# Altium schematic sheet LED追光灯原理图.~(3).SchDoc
size A3
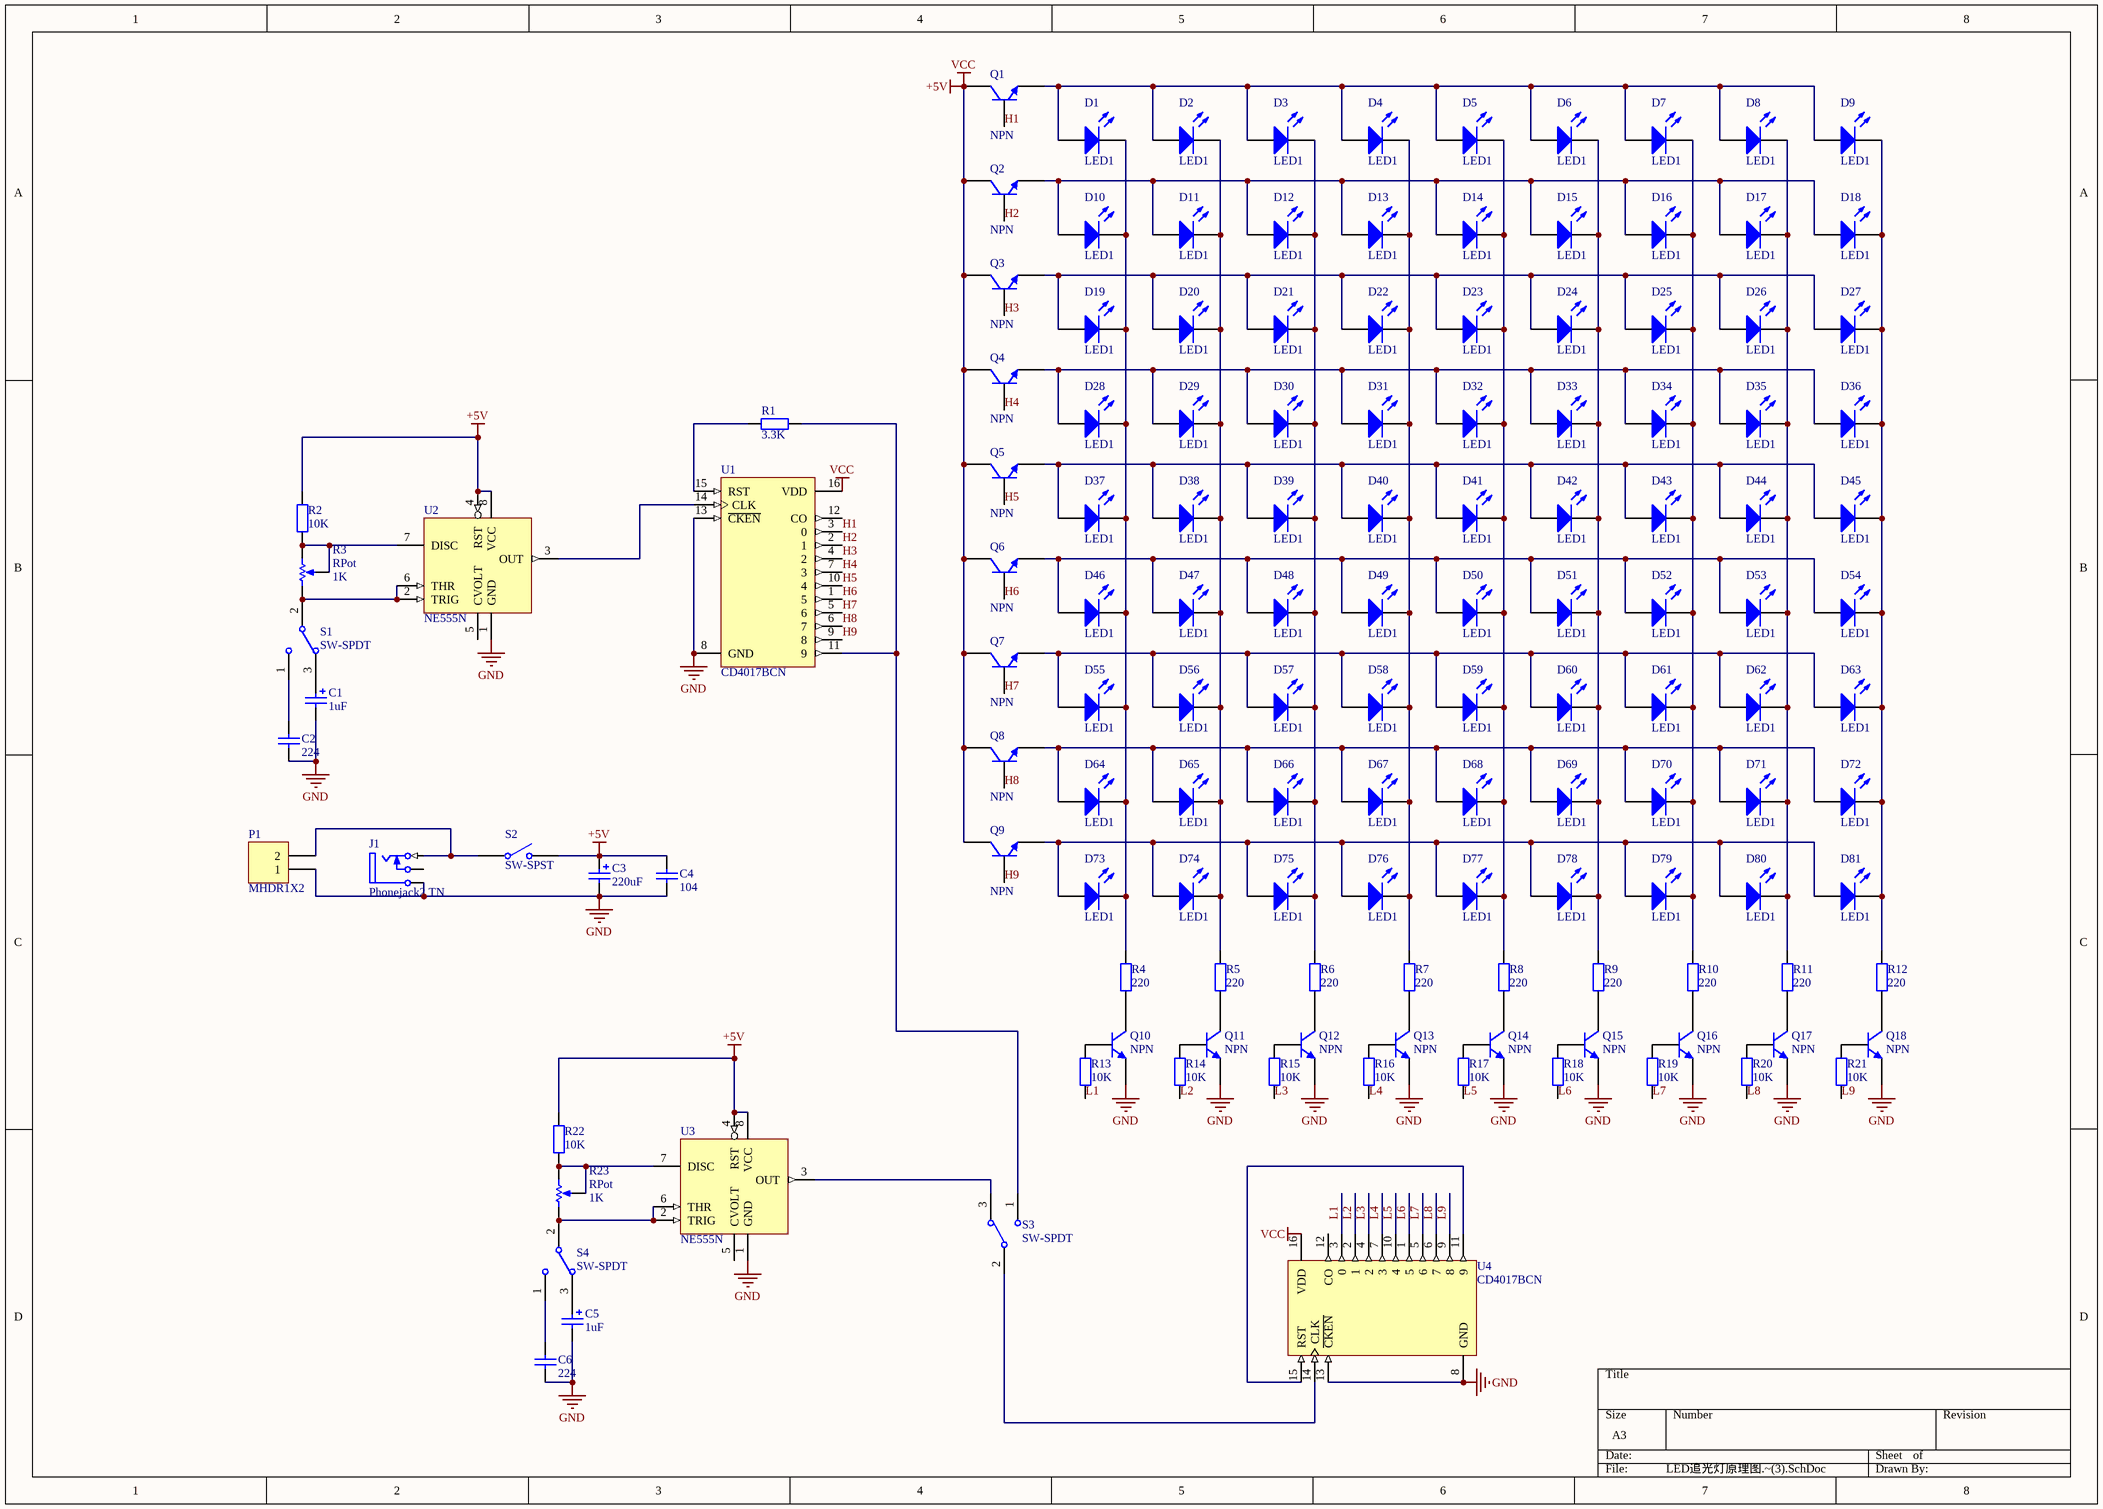
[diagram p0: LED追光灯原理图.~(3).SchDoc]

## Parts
C1  value 1uF  [POLAR0.8]  (hidden comment: Cap Pol2)
C2  value 224  [RAD-0.3]  (hidden comment: Cap)
C3  value 220uF  [POLAR0.8]  (hidden comment: Cap Pol2)
C4  value 104  [RAD-0.3]  (hidden comment: Cap)
C5  value 1uF  [POLAR0.8]  (hidden comment: Cap Pol2)
C6  value 224  [RAD-0.3]  (hidden comment: Cap)
D1  LED1  [LED-1]
D2  LED1  [LED-1]
D3  LED1  [LED-1]
D4  LED1  [LED-1]
D5  LED1  [LED-1]
D6  LED1  [LED-1]
D7  LED1  [LED-1]
D8  LED1  [LED-1]
D9  LED1  [LED-1]
D10  LED1  [LED-1]
D11  LED1  [LED-1]
D12  LED1  [LED-1]
D13  LED1  [LED-1]
D14  LED1  [LED-1]
D15  LED1  [LED-1]
D16  LED1  [LED-1]
D17  LED1  [LED-1]
D18  LED1  [LED-1]
D19  LED1  [LED-1]
D20  LED1  [LED-1]
D21  LED1  [LED-1]
D22  LED1  [LED-1]
D23  LED1  [LED-1]
D24  LED1  [LED-1]
D25  LED1  [LED-1]
D26  LED1  [LED-1]
D27  LED1  [LED-1]
D28  LED1  [LED-1]
D29  LED1  [LED-1]
D30  LED1  [LED-1]
D31  LED1  [LED-1]
D32  LED1  [LED-1]
D33  LED1  [LED-1]
D34  LED1  [LED-1]
D35  LED1  [LED-1]
D36  LED1  [LED-1]
D37  LED1  [LED-1]
D38  LED1  [LED-1]
D39  LED1  [LED-1]
D40  LED1  [LED-1]
D41  LED1  [LED-1]
D42  LED1  [LED-1]
D43  LED1  [LED-1]
D44  LED1  [LED-1]
D45  LED1  [LED-1]
D46  LED1  [LED-1]
D47  LED1  [LED-1]
D48  LED1  [LED-1]
D49  LED1  [LED-1]
D50  LED1  [LED-1]
D51  LED1  [LED-1]
D52  LED1  [LED-1]
D53  LED1  [LED-1]
D54  LED1  [LED-1]
D55  LED1  [LED-1]
D56  LED1  [LED-1]
D57  LED1  [LED-1]
D58  LED1  [LED-1]
D59  LED1  [LED-1]
D60  LED1  [LED-1]
D61  LED1  [LED-1]
D62  LED1  [LED-1]
D63  LED1  [LED-1]
D64  LED1  [LED-1]
D65  LED1  [LED-1]
D66  LED1  [LED-1]
D67  LED1  [LED-1]
D68  LED1  [LED-1]
D69  LED1  [LED-1]
D70  LED1  [LED-1]
D71  LED1  [LED-1]
D72  LED1  [LED-1]
D73  LED1  [LED-1]
D74  LED1  [LED-1]
D75  LED1  [LED-1]
D76  LED1  [LED-1]
D77  LED1  [LED-1]
D78  LED1  [LED-1]
D79  LED1  [LED-1]
D80  LED1  [LED-1]
D81  LED1  [LED-1]
J1  Phonejack2 TN  [JACK/6-V3A]
P1  MHDR1X2  [MHDR1X2]
Q1  NPN  [TO-226-AA]
Q2  NPN  [TO-226-AA]
Q3  NPN  [TO-226-AA]
Q4  NPN  [TO-226-AA]
Q5  NPN  [TO-226-AA]
Q6  NPN  [TO-226-AA]
Q7  NPN  [TO-226-AA]
Q8  NPN  [TO-226-AA]
Q9  NPN  [TO-226-AA]
Q10  NPN  [TO-226-AA]
Q11  NPN  [TO-226-AA]
Q12  NPN  [TO-226-AA]
Q13  NPN  [TO-226-AA]
Q14  NPN  [TO-226-AA]
Q15  NPN  [TO-226-AA]
Q16  NPN  [TO-226-AA]
Q17  NPN  [TO-226-AA]
Q18  NPN  [TO-226-AA]
R1  value 3.3K  [AXIAL-0.4]  (hidden comment: Res2)
R2  value 10K  [AXIAL-0.4]  (hidden comment: Res2)
R3  RPot  value 1K  [VR5]
R4  value 220  [AXIAL-0.4]  (hidden comment: Res2)
R5  value 220  [AXIAL-0.4]  (hidden comment: Res2)
R6  value 220  [AXIAL-0.4]  (hidden comment: Res2)
R7  value 220  [AXIAL-0.4]  (hidden comment: Res2)
R8  value 220  [AXIAL-0.4]  (hidden comment: Res2)
R9  value 220  [AXIAL-0.4]  (hidden comment: Res2)
R10  value 220  [AXIAL-0.4]  (hidden comment: Res2)
R11  value 220  [AXIAL-0.4]  (hidden comment: Res2)
R12  value 220  [AXIAL-0.4]  (hidden comment: Res2)
R13  value 10K  [AXIAL-0.4]  (hidden comment: Res2)
R14  value 10K  [AXIAL-0.4]  (hidden comment: Res2)
R15  value 10K  [AXIAL-0.4]  (hidden comment: Res2)
R16  value 10K  [AXIAL-0.4]  (hidden comment: Res2)
R17  value 10K  [AXIAL-0.4]  (hidden comment: Res2)
R18  value 10K  [AXIAL-0.4]  (hidden comment: Res2)
R19  value 10K  [AXIAL-0.4]  (hidden comment: Res2)
R20  value 10K  [AXIAL-0.4]  (hidden comment: Res2)
R21  value 10K  [AXIAL-0.4]  (hidden comment: Res2)
R22  value 10K  [AXIAL-0.4]  (hidden comment: Res2)
R23  RPot  value 1K  [VR5]
S1  SW-SPDT  [TL36WW15050]
S2  SW-SPST  [SPST-2]
S3  SW-SPDT  [TL36WW15050]
S4  SW-SPDT  [TL36WW15050]
U1  CD4017BCN  [N16E]
U2  NE555N  [DIP8]
U3  NE555N  [DIP8]
U4  CD4017BCN  [N16E]

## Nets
+5V: C3.1 C4.2 Q1.1(C) Q2.1(C) Q3.1(C) Q4.1(C) Q5.1(C) Q6.1(C) Q7.1(C) Q8.1(C) Q9.1(C) R2.1 R22.1 S2.2(NO) U1.16(VDD) U2.4(RST) U2.8(VCC) U3.4(RST) U3.8(VCC) U4.16(VDD)  [also labelled VCC]
GND: C1.2 C2.2 C3.2 C4.1 C5.2 C6.2 J1.5(S) P1.1 Q10.3(E) Q11.3(E) Q12.3(E) Q13.3(E) Q14.3(E) Q15.3(E) Q16.3(E) Q17.3(E) Q18.3(E) U1.8(GND) U1.13(~{CKEN}) U2.1(GND) U3.1(GND) U4.8(GND) U4.13(~{CKEN})
H1: Q1.2(B) U1.3(0)
H2: Q2.2(B) U1.2(1)
H3: Q3.2(B) U1.4(2)
H4: Q4.2(B) U1.7(3)
H5: Q5.2(B) U1.10(4)
H6: Q6.2(B) U1.1(5)
H7: Q7.2(B) U1.5(6)
H8: Q8.2(B) U1.6(7)
H9: Q9.2(B) U1.9(8)
L1: R13.2 U4.3(0)
L2: R14.2 U4.2(1)
L3: R15.2 U4.4(2)
L4: R16.2 U4.7(3)
L5: R17.2 U4.10(4)
L6: R18.2 U4.1(5)
L7: R19.2 U4.5(6)
L8: R20.2 U4.6(7)
L9: R21.2 U4.9(8)
NetC1_1: C1.1 S1.3
NetC2_1: C2.1 S1.1
NetC5_1: C5.1 S4.3
NetC6_1: C6.1 S4.1
NetD1_1: D1.1(A) D2.1(A) D3.1(A) D4.1(A) D5.1(A) D6.1(A) D7.1(A) D8.1(A) D9.1(A) Q1.3(E)
NetD1_2: D1.2(K) D10.2(K) D19.2(K) D28.2(K) D37.2(K) D46.2(K) D55.2(K) D64.2(K) D73.2(K) R4.2
NetD2_2: D2.2(K) D11.2(K) D20.2(K) D29.2(K) D38.2(K) D47.2(K) D56.2(K) D65.2(K) D74.2(K) R5.2
NetD3_2: D3.2(K) D12.2(K) D21.2(K) D30.2(K) D39.2(K) D48.2(K) D57.2(K) D66.2(K) D75.2(K) R6.2
NetD4_2: D4.2(K) D13.2(K) D22.2(K) D31.2(K) D40.2(K) D49.2(K) D58.2(K) D67.2(K) D76.2(K) R7.2
NetD5_2: D5.2(K) D14.2(K) D23.2(K) D32.2(K) D41.2(K) D50.2(K) D59.2(K) D68.2(K) D77.2(K) R8.2
NetD6_2: D6.2(K) D15.2(K) D24.2(K) D33.2(K) D42.2(K) D51.2(K) D60.2(K) D69.2(K) D78.2(K) R9.2
NetD7_2: D7.2(K) D16.2(K) D25.2(K) D34.2(K) D43.2(K) D52.2(K) D61.2(K) D70.2(K) D79.2(K) R10.2
NetD8_2: D8.2(K) D17.2(K) D26.2(K) D35.2(K) D44.2(K) D53.2(K) D62.2(K) D71.2(K) D80.2(K) R11.2
NetD9_2: D9.2(K) D18.2(K) D27.2(K) D36.2(K) D45.2(K) D54.2(K) D63.2(K) D72.2(K) D81.2(K) R12.2
NetD10_1: D10.1(A) D11.1(A) D12.1(A) D13.1(A) D14.1(A) D15.1(A) D16.1(A) D17.1(A) D18.1(A) Q2.3(E)
NetD19_1: D19.1(A) D20.1(A) D21.1(A) D22.1(A) D23.1(A) D24.1(A) D25.1(A) D26.1(A) D27.1(A) Q3.3(E)
NetD28_1: D28.1(A) D29.1(A) D30.1(A) D31.1(A) D32.1(A) D33.1(A) D34.1(A) D35.1(A) D36.1(A) Q4.3(E)
NetD37_1: D37.1(A) D38.1(A) D39.1(A) D40.1(A) D41.1(A) D42.1(A) D43.1(A) D44.1(A) D45.1(A) Q5.3(E)
NetD46_1: D46.1(A) D47.1(A) D48.1(A) D49.1(A) D50.1(A) D51.1(A) D52.1(A) D53.1(A) D54.1(A) Q6.3(E)
NetD55_1: D55.1(A) D56.1(A) D57.1(A) D58.1(A) D59.1(A) D60.1(A) D61.1(A) D62.1(A) D63.1(A) Q7.3(E)
NetD64_1: D64.1(A) D65.1(A) D66.1(A) D67.1(A) D68.1(A) D69.1(A) D70.1(A) D71.1(A) D72.1(A) Q8.3(E)
NetD73_1: D73.1(A) D74.1(A) D75.1(A) D76.1(A) D77.1(A) D78.1(A) D79.1(A) D80.1(A) D81.1(A) Q9.3(E)
NetJ1_1: J1.1(T) P1.2 S2.1(COMMON)
NetQ10_1: Q10.1(C) R4.1
NetQ10_2: Q10.2(B) R13.1
NetQ11_1: Q11.1(C) R5.1
NetQ11_2: Q11.2(B) R14.1
NetQ12_1: Q12.1(C) R6.1
NetQ12_2: Q12.2(B) R15.1
NetQ13_1: Q13.1(C) R7.1
NetQ13_2: Q13.2(B) R16.1
NetQ14_1: Q14.1(C) R8.1
NetQ14_2: Q14.2(B) R17.1
NetQ15_1: Q15.1(C) R9.1
NetQ15_2: Q15.2(B) R18.1
NetQ16_1: Q16.1(C) R10.1
NetQ16_2: Q16.2(B) R19.1
NetQ17_1: Q17.1(C) R11.1
NetQ17_2: Q17.2(B) R20.1
NetQ18_1: Q18.1(C) R12.1
NetQ18_2: Q18.2(B) R21.1
NetR1_1: R1.1 U1.15(RST)
NetR1_2: R1.2 S3.1 U1.11(9)
NetR2_2: R2.2 R3.2(BOT) R3.3(TAP) U2.7(DISC)
NetR3_1: R3.1(TOP) S1.2 U2.2(TRIG) U2.6(THR)
NetR22_2: R22.2 R23.2(BOT) R23.3(TAP) U3.7(DISC)
NetR23_1: R23.1(TOP) S4.2 U3.2(TRIG) U3.6(THR)
NetS3_2: S3.2 U4.14(CLK)
NetS3_3: S3.3 U3.3(OUT)
NetU1_14: U1.14(CLK) U2.3(OUT)
NetU4_11: U4.11(9) U4.15(RST)

Not connected (* = marked no-connect by the designer): J1 2(TN); U1 12(CO); U2 5(CVOLT); U3 5(CVOLT); U4 12(CO)

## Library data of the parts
C1 C3 C5 = Cap Pol2: Polarized Capacitor (Axial)
C2 C4 C6 = Cap: Capacitor
D1-D81 = LED1: Typical RED GaAs LED
J1 = Phonejack2 TN: Jack Socket, 1/4" [6.5mm], Thru-Hole, Vertical, 2-Conductor with Tip closed; PackageDocument: 2003; PCB_Layout: Complies with manufacturer's recommendation.; DrillAndSlotSize: Corresponds to nominal value.
P1 = MHDR1X2: Header, 2-Pin
Q1-Q18 = NPN: NPN Bipolar Transistor
R1 R2 R4-R22 = Res2: Resistor
R3 R23 = RPot: Potentiometer; Sim Note: Enter the Resistance value and the set point into parameter fields.; Set Position: 0.5
S1 S3 S4 = SW-SPDT: SPDT Subminiature Toggle Switch, Right Angle Mounting, Vertical Actuation
S2 = SW-SPST: Single-Pole, Single-Throw Switch
U1 U4 = CD4017BCN: Decade Counter/Divider with 10 Decoded Outputs
U2 U3 = NE555N: General-Purpose Single Bipolar Timer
